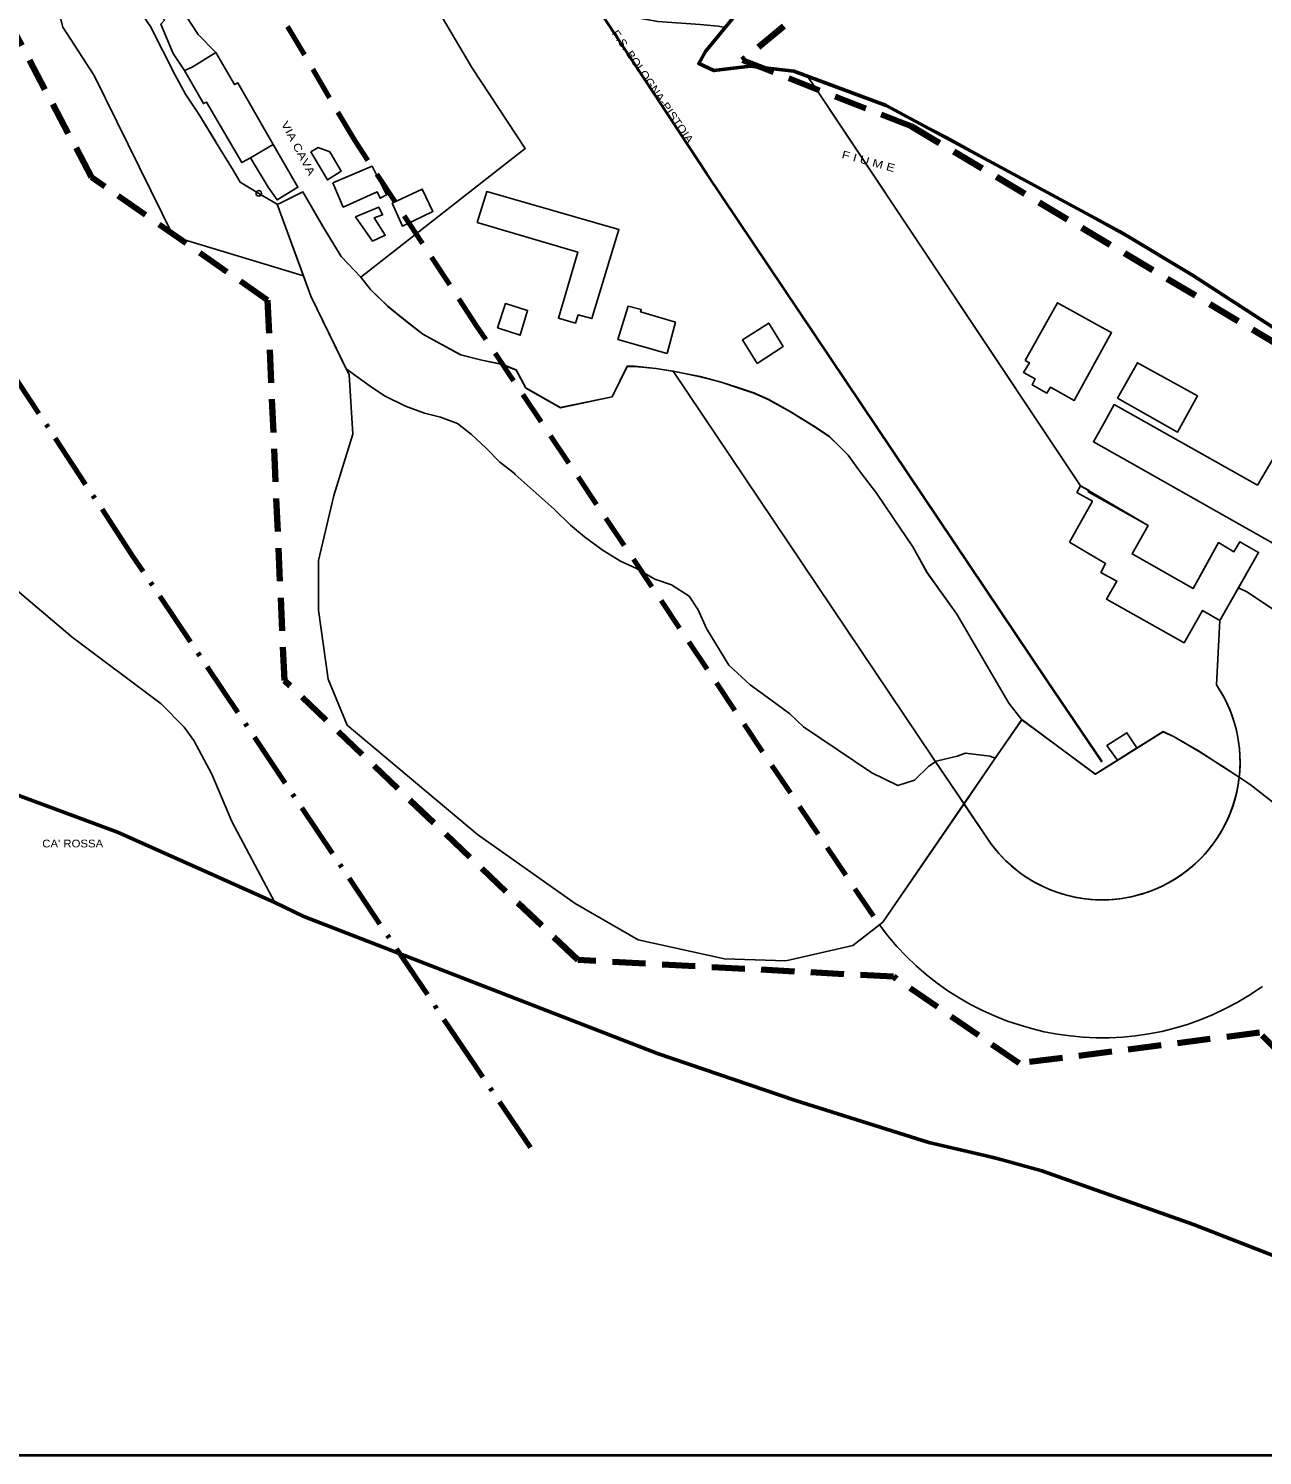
# Model space of a CAD drawing. Extents: x 654952 to 658955, y 890426 to 894481.
# Drawn here: x 658161 to 658609, y 890426 to 890943 of the extents above; entities that cross this region are included whole.
import ezdxf

# ---------------------------------------------------------------- set-up
doc = ezdxf.new("R2010")
doc.units = 0
doc.header["$LTSCALE"] = 4
doc.header["$PDMODE"] = 32
doc.header["$PDSIZE"] = 2
doc.linetypes.add('DOT_DASHED', pattern=[7.7, 5, -1.2, 0.3, -1.2])
doc.linetypes.add('MEDIUM_DASHED', pattern=[4.5, 3, -1.5])
for name, color, linetype, lineweight in [('1', 7, 'Continuous', 25), ('29', 7, 'Continuous', 25), ('35', 7, 'Continuous', 25), ('4', 7, 'Continuous', 25), ('45', 7, 'Continuous', 25), ('55', 7, 'Continuous', 25), ('59', 7, 'Continuous', 53), ('6', 7, 'Continuous', 25), ('60', 7, 'Continuous', 35), ('7', 7, 'MEDIUM_DASHED', 100)]:
    doc.layers.add(name, color=color, linetype=linetype, lineweight=lineweight)
doc.layers.add('58', color=7, linetype='Continuous')

msp = doc.modelspace()

# ---------------------------------------------------------------- linework, layer by layer
at = {"layer": '1'}
msp.add_line((658453.98, 890910.72), (658542.85, 890777.44), dxfattribs=at)
for points in [[(658144.37, 890983.94), (658154.14, 890977.98), (658161.52, 890990.5), (658162.91, 890989.74), (658177.71, 890975.4), (658182.65, 890970.82), (658190.16, 890960.7), (658196.63, 890954.23), (658203.08, 890947.87), (658204.42, 890945.86), (658205.72, 890943.95), (658214.64, 890926.33)], [(658404.44, 890930.41), (658406.91, 890934.75), (658414.05, 890943.51), (658411.52, 890943.99), (658404.98, 890944.67), (658389.6, 890945.68), (658372.54, 890948.71), (658364.14, 890949.78), (658351.24, 890952.81), (658343.66, 890956.03), (658335.11, 890960.84)], [(658423.05, 890929.48), (658409.9, 890927.87), (658404.44, 890930.41)], [(658734.45, 890511.82), (658722.78, 890480.06), (658736.33, 890473.12), (658752.96, 890521.61), (658761.95, 890519.26), (658765.57, 890535.45), (658773.72, 890567.09), (658775.59, 890594.61), (658758.58, 890658.97), (658744.97, 890694.47), (658733.05, 890720.87), (658710.93, 890746.45), (658684.67, 890777.43), (658645.53, 890812.09), (658603.84, 890840.99), (658568.96, 890862.45), (658494.56, 890903.83), (658472.38, 890915.2), (658438.87, 890927.61), (658423.05, 890929.48)], [(658214.64, 890926.33), (658218.42, 890919.34), (658223.22, 890912.19), (658229.44, 890902.01), (658235.67, 890891.84), (658238.22, 890887.44), (658244.95, 890883.42)], [(658645.53, 890812.09), (658603.84, 890840.99), (658568.96, 890862.45), (658494.56, 890903.83), (658472.38, 890915.2), (658443.99, 890925.71), (658448.98, 890918.22), (658453.98, 890910.72)], [(658600.07, 890740.44), (658603.34, 890738.83), (658624.52, 890724.75), (658645.68, 890709.35), (658672.24, 890689.64), (658686.53, 890672.4), (658723.74, 890628.69), (658738.84, 890615.48), (658747.88, 890610.82), (658767.93, 890596.66), (658775.17, 890588.4), (658775.59, 890594.61), (658758.58, 890658.97), (658744.97, 890694.47), (658733.05, 890720.87), (658710.93, 890746.45), (658684.67, 890777.43), (658645.53, 890812.09), (658603.84, 890840.99), (658568.96, 890862.45), (658494.56, 890903.83), (658472.38, 890915.2), (658443.99, 890925.71)], [(658443.99, 890925.71), (658448.98, 890918.22), (658453.98, 890910.72)], [(658453.98, 890910.72), (658542.85, 890777.44), (658567.33, 890763), (658561.5, 890752.72), (658583.67, 890740.2), (658587.28, 890746.72)], [(658244.95, 890883.42), (658251.66, 890879.46), (658252.47, 890879.79), (658260.92, 890883.93), (658268.23, 890871.33), (658274.77, 890860.54), (658281.88, 890853.09)], [(658281.88, 890853.09), (658285.47, 890848.53), (658291.76, 890842.46), (658298.59, 890836.8), (658304.4, 890832.38), (658318.14, 890824.87), (658325.82, 890822.96), (658333.13, 890821.39), (658338.29, 890819.37)], [(658338.29, 890819.37), (658341.72, 890812.83), (658354.26, 890805.72), (658372.98, 890809.62), (658378.45, 890820.71), (658381.12, 890820.68)], [(658381.12, 890820.68), (658388.94, 890819.92), (658396.93, 890818.61), (658404.94, 890816.93), (658412.6, 890814.98), (658418.22, 890813.07), (658424.38, 890811.03), (658429.56, 890808.76), (658437.64, 890804.27), (658446.06, 890799.09), (658451.75, 890795.25), (658455.7, 890791.41), (658458.64, 890788.49)], [(658458.64, 890788.49), (658463.32, 890782.05), (658468.89, 890774.79), (658474.93, 890765.75), (658482.01, 890755.23), (658487.22, 890745.92), (658497.95, 890730.82), (658516.82, 890698.56), (658521.53, 890692.55), (658548.19, 890672.82), (658572.74, 890688.25)], [(658542.85, 890777.44), (658567.33, 890763), (658561.5, 890752.72), (658583.67, 890740.2), (658587.28, 890746.72)], [(658587.28, 890746.72), (658592.87, 890756.8), (658598.39, 890753.48), (658600.55, 890757.16), (658607.33, 890753.26), (658600.07, 890740.44)], [(658587.28, 890746.72), (658592.87, 890756.8), (658598.39, 890753.48), (658600.55, 890757.16), (658607.33, 890753.26), (658600.07, 890740.44)], [(658600.07, 890740.44), (658603.34, 890738.83), (658624.52, 890724.75)], [(658572.74, 890688.25), (658576.75, 890686.35), (658585.54, 890681.27), (658593.98, 890675.84), (658604.34, 890669.07), (658613.77, 890661.75)]]:
    msp.add_lwpolyline(points, dxfattribs=at)
msp.add_point((658244.95, 890883.42), dxfattribs=at)
at = {"layer": '29'}
for p, q in [((658396.9, 890818.66), (658396.93, 890818.61)), ((658474.9, 890765.8), (658468.89, 890774.79)), ((658497.92, 890730.87), (658487.2, 890745.96)), ((658489.14, 890679.06), (658490.26, 890677.4)), ((658500.57, 890662.11), (658490.26, 890677.4))]:
    msp.add_line(p, q, dxfattribs=at)
for points in [[(658395.2, 890818.94), (658388.91, 890819.97), (658381.09, 890820.73), (658378.42, 890820.76), (658372.98, 890809.62), (658354.23, 890805.77), (658341.69, 890812.88), (658338.26, 890819.42), (658333.09, 890821.49), (658325.79, 890823.01), (658318.11, 890824.92), (658304.37, 890832.43), (658298.56, 890836.85), (658291.73, 890842.51), (658285.44, 890848.58), (658281.88, 890853.09), (658274.77, 890860.54), (658268.2, 890871.38), (658260.92, 890883.93), (658252.47, 890879.79), (658251.66, 890879.46), (658263.82, 890846.16), (658276.67, 890819.81)], [(658276.67, 890819.81), (658277.7, 890817.69), (658279.08, 890796.16), (658272.14, 890773.94), (658266.59, 890750.33), (658266.59, 890732.27), (658270.06, 890707.27), (658277, 890690.61), (658324.2, 890651.02)], [(658490.26, 890677.4), (658487.87, 890675.79), (658482.63, 890670.75), (658476.58, 890668.78), (658467.21, 890673.37), (658442.34, 890690.05), (658437.4, 890694.69), (658430.6, 890699.87), (658423.01, 890705.28), (658415.29, 890712.39), (658407.26, 890725.63), (658404.27, 890732.41), (658400.96, 890737.37), (658394.56, 890741.53), (658388.54, 890743.54), (658381.83, 890747.44), (658376.12, 890750.06), (658369.83, 890753.97), (658363.04, 890758.93), (658357.94, 890763.17), (658352.05, 890768.92), (658337.9, 890781.56), (658337.56, 890781.98), (658332.37, 890785.95), (658327.42, 890791.08), (658322.07, 890795.98), (658317.01, 890799.98), (658310.76, 890802.35), (658305.01, 890803.78), (658298.1, 890806.25), (658290.57, 890810.05), (658285.35, 890813.58), (658280.14, 890817.31), (658276.67, 890819.81)], [(658276.67, 890819.81), (658280.14, 890817.31), (658285.35, 890813.58), (658290.57, 890810.05), (658298.1, 890806.25), (658305.01, 890803.78), (658310.76, 890802.35), (658317.01, 890799.98), (658322.07, 890795.98), (658327.42, 890791.08), (658332.37, 890785.95), (658337.56, 890781.98), (658337.9, 890781.56), (658352.05, 890768.92), (658357.94, 890763.17), (658363.04, 890758.93), (658369.83, 890753.97), (658376.12, 890750.06)], [(658396.9, 890818.66), (658395.2, 890818.94), (658489.14, 890679.06)], [(658490.26, 890677.4), (658489.14, 890679.06), (658395.2, 890818.94)], [(658429.58, 890808.78), (658429.53, 890808.81), (658424.34, 890811.13), (658418.19, 890813.12), (658412.57, 890815.03), (658404.9, 890817.03), (658396.9, 890818.66)], [(658429.56, 890808.76), (658424.38, 890811.03), (658418.22, 890813.07), (658412.6, 890814.98), (658404.94, 890816.93), (658396.93, 890818.61)], [(658396.93, 890818.61), (658404.94, 890816.93), (658412.6, 890814.98), (658418.22, 890813.07), (658424.38, 890811.03), (658429.56, 890808.76), (658429.58, 890808.78)], [(658458.61, 890788.54), (658451.71, 890795.35), (658446.03, 890799.14), (658437.61, 890804.32), (658429.58, 890808.78)], [(658468.89, 890774.79), (658463.32, 890782.05), (658458.64, 890788.49)], [(658487.2, 890745.96), (658482.01, 890755.23), (658474.93, 890765.75)], [(658376.12, 890750.06), (658381.83, 890747.44), (658388.54, 890743.54), (658394.56, 890741.53), (658400.96, 890737.37), (658404.27, 890732.41), (658407.26, 890725.63), (658415.29, 890712.39), (658423.01, 890705.28), (658430.6, 890699.87), (658437.4, 890694.69), (658442.34, 890690.05), (658467.21, 890673.37), (658476.58, 890668.78), (658482.63, 890670.75), (658487.87, 890675.79), (658490.26, 890677.4)], [(658511.91, 890678.63), (658521.5, 890692.6), (658516.8, 890698.6), (658497.95, 890730.82)], [(658490.26, 890677.4), (658490.48, 890677.55), (658498.07, 890679.43), (658501.06, 890680.49), (658509.93, 890679.39), (658511.91, 890678.63)], [(658500.57, 890662.11), (658511.91, 890678.63), (658509.93, 890679.39), (658501.06, 890680.49), (658498.07, 890679.43)], [(658498.07, 890679.43), (658490.48, 890677.55), (658490.26, 890677.4), (658500.57, 890662.11)], [(658324.2, 890651.02), (658359.59, 890626.02), (658382.5, 890612.83), (658413.73, 890605.89), (658435.94, 890605.19), (658460.23, 890610.75), (658471.13, 890619.23), (658500.57, 890662.11)]]:
    msp.add_lwpolyline(points, dxfattribs=at)
at = {"layer": '35'}
for p, q in [((658229.41, 890902.06), (658223.22, 890912.19)), ((658261.14, 890853.52), (658213.99, 890867.74)), ((658509.2, 890649.33), (658500.57, 890662.11))]:
    msp.add_line(p, q, dxfattribs=at)
for points in [[(658213.99, 890867.74), (658185.33, 890926.17), (658173.89, 890943.74), (658167.04, 890971.14), (658161.52, 890990.5), (658154.14, 890977.98), (658144.37, 890983.94), (658152.75, 890997.52), (658139.53, 891006.49)], [(658161.52, 890990.5), (658167.04, 890971.14), (658173.89, 890943.74), (658185.33, 890926.17), (658213.99, 890867.74)], [(658223.22, 890912.19), (658218.42, 890919.34), (658214.64, 890926.33), (658205.72, 890943.95), (658204.42, 890945.86), (658203.08, 890947.87)], [(658244.95, 890883.42), (658238.22, 890887.44), (658235.67, 890891.84), (658229.44, 890902.01)], [(658213.99, 890867.74), (658261.14, 890853.52), (658251.66, 890879.46), (658244.95, 890883.42)], [(658044.62, 890869.41), (658053.99, 890858.05), (658072.44, 890837.18), (658093.46, 890800.73), (658145.37, 890749.45), (658177.27, 890722.55), (658209.51, 890698.32), (658217.94, 890689.89), (658221.35, 890685.08), (658227.97, 890672.83), (658235.17, 890655.67), (658250.77, 890626.38), (658261.33, 890621.22), (658389.5, 890571.65), (658439.45, 890554.58)], [(658469.92, 890618.28), (658460.23, 890610.75), (658435.94, 890605.19), (658413.73, 890605.89), (658382.5, 890612.83), (658359.59, 890626.02), (658324.2, 890651.02), (658277, 890690.61), (658270.06, 890707.27), (658266.59, 890732.27), (658266.59, 890750.33), (658272.14, 890773.94), (658279.08, 890796.16), (658277.7, 890817.69), (658263.82, 890846.16), (658261.14, 890853.52)], [(658064.38, 890699.85), (658193.76, 890651.87), (658250.77, 890626.38), (658235.17, 890655.67), (658227.97, 890672.83), (658221.35, 890685.08), (658217.94, 890689.89), (658209.51, 890698.32), (658177.27, 890722.55), (658145.37, 890749.45)], [(658600.33, 890671.74), (658593.94, 890675.94), (658585.51, 890681.32), (658576.71, 890686.45), (658572.71, 890688.3), (658548.15, 890672.92), (658521.49, 890692.65), (658500.56, 890662.13), (658509.2, 890649.33)], [(658613.74, 890661.8), (658604.31, 890669.12), (658600.33, 890671.74)], [(658500.56, 890662.13), (658471.13, 890619.23), (658469.92, 890618.28)], [(658439.45, 890554.58), (658487.84, 890539.37), (658528.8, 890529.12), (658583.71, 890509.56), (658626.83, 890492.8), (658673.05, 890479.76), (658699.42, 890463), (658709.42, 890459.89)]]:
    msp.add_lwpolyline(points, dxfattribs=at)
for radius, start, end in [(50, 292.3219, 353.6142), (50, 304.0044, 353.6142), (50, 214.0081, 292.3219), (50, 214.0081, 292.3219), (50, 292.3219, 304.0044), (100, 216.1693, 305.0715), (100, 216.1693, 305.0715), (100, 305.0715, 305.5264), (100, 305.0715, 305.5264)]:
    msp.add_arc((658550.64, 890677.3), radius, start, end, dxfattribs=at)
msp.add_point((658244.95, 890883.42), dxfattribs=at)
at = {"layer": '4'}
for points in [[(658229.43, 890934.5), (658220.79, 890929.13), (658218.02, 890927.98), (658224.88, 890915.98), (658226, 890916.5), (658238.81, 890894.62), (658241.96, 890896.28), (658250.2, 890901.18), (658237.34, 890923.5), (658236.18, 890922.84)], [(658241.96, 890896.28), (658250.2, 890901.18), (658256.38, 890890.48), (658259.16, 890885.64), (658251.6, 890881.06), (658248.37, 890885.62)], [(658263.81, 890898.54), (658266.51, 890900), (658270.7, 890898.48), (658274.82, 890891.54), (658269.8, 890888.28)], [(658271.77, 890887.24), (658286.02, 890893.28), (658290.15, 890885.02), (658291.25, 890882.84), (658288.89, 890881.64), (658287.8, 890884), (658275.59, 890878.46)], [(658293.31, 890879.88), (658297.08, 890871.54), (658308.08, 890876.86), (658304.23, 890884.98)], [(658293.31, 890879.88), (658304.23, 890884.98), (658308.08, 890876.86), (658297.08, 890871.54)], [(658293.31, 890879.88), (658304.23, 890884.98), (658308.08, 890876.86), (658297.08, 890871.54)], [(658324.09, 890872.82), (658327.6, 890884.08), (658375.48, 890870.3), (658365.69, 890838.04), (658360.7, 890839.38), (658359.71, 890836.38), (658353.55, 890838.16), (658360.65, 890862.06)], [(658279.98, 890874.94), (658288.44, 890878.44), (658289.81, 890875.62), (658286.79, 890874.54), (658290.77, 890868.22), (658286.17, 890866.14)], [(658331.53, 890834.7), (658334.36, 890843.48), (658342.38, 890841), (658339.66, 890832.02)], [(658392.96, 890825.38), (658375.11, 890830.46), (658378.81, 890842.5), (658383.61, 890841.28), (658383.37, 890840.54), (658395.98, 890836.74)], [(658522.79, 890822.84), (658534.42, 890843.8), (658551.49, 890834.38), (658554.06, 890832.96), (658540.53, 890808.34), (658531.87, 890813.14), (658530.64, 890811.04), (658525.25, 890814.06), (658526.4, 890816.16), (658522.19, 890818.5), (658524.25, 890822.04)], [(658425.54, 890821.7), (658420.27, 890830.28), (658429.77, 890836.34), (658435, 890827.96)], [(658556.25, 890809.14), (658563.42, 890822.04), (658585.22, 890810.02), (658577.95, 890796.84)], [(658538.83, 890756.94), (658547.09, 890771.88), (658541.52, 890775.04), (658542.85, 890777.44), (658545.9, 890775.72), (658545.59, 890775.18), (658567.33, 890763), (658561.5, 890752.72), (658583.67, 890740.2), (658592.87, 890756.8), (658598.39, 890753.48), (658600.55, 890757.16), (658607.33, 890753.26), (658593.32, 890728.54), (658587.06, 890732.24), (658580.41, 890720.52), (658552.22, 890736.36), (658555.93, 890742.9), (658550.17, 890746.04), (658551.86, 890749.22)], [(658552.34, 890683.32), (658556.16, 890677.9), (658563.26, 890682.36), (658559.64, 890687.9)]]:
    msp.add_lwpolyline(points, close=True, dxfattribs=at)
for points in [[(658551.32, 890800.26), (658554.98, 890806.86), (658606.97, 890777.62)], [(658558.02, 890787.4), (658547.5, 890793.3), (658551.32, 890800.26)], [(658606.97, 890777.62), (658613.61, 890788.88), (658640.7, 890773.92), (658627.61, 890750.42), (658619.84, 890754.54), (658618.89, 890753.02), (658558.02, 890787.4)]]:
    msp.add_lwpolyline(points, dxfattribs=at)
at = {"layer": '45', "linetype": 'MEDIUM_DASHED', "lineweight": 70}
msp.add_lwpolyline([(658467.75, 890621.37), (658447.66, 890651.14), (658324.04, 890835.2), (658279.74, 890902.58), (658248.15, 890956.2), (658220.13, 891019.53), (658157.73, 891276.4)], dxfattribs=at)
at = {"layer": '45', "linetype": 'DOT_DASHED', "lineweight": 70}
msp.add_lwpolyline([(658343.4, 890537.48), (658323.23, 890567.38), (658199.11, 890752.18), (658152.38, 890823.25), (658114.5, 890887.55), (658077.53, 890971.09), (658011.97, 891240.99)], dxfattribs=at)
at = {"layer": '45', "lineweight": 40}
msp.add_lwpolyline([(658550.65, 890677.3), (658530.62, 890706.98), (658407.33, 890890.55), (658364.65, 890955.46), (658337.25, 891001.97), (658315.22, 891051.75), (658272.64, 891227.84)], dxfattribs=at)
msp.add_lwpolyline([(658550.65, 890677.3), (658530.62, 890706.98), (658407.33, 890890.55), (658364.65, 890955.46), (658337.25, 891001.97), (658315.22, 891051.75), (658272.64, 891227.84)], dxfattribs=at)
at = {"layer": '45'}
for points in [[(658509.2, 890649.33), (658489.14, 890679.06), (658395.17, 890818.98), (658388.91, 890819.97), (658381.09, 890820.73), (658378.45, 890820.71), (658372.98, 890809.62), (658354.26, 890805.72), (658341.72, 890812.83), (658338.29, 890819.37), (658333.13, 890821.39), (658325.82, 890822.96), (658318.14, 890824.87), (658304.4, 890832.38), (658291.76, 890842.46), (658285.47, 890848.53), (658281.88, 890853.09), (658341.53, 890899.7), (658322.2, 890929.02), (658292.7, 890979.09)], [(658430.14, 890963.41), (658406.87, 890934.85), (658404.4, 890930.51), (658409.9, 890927.87), (658423.01, 890929.58), (658438.87, 890927.61), (658443.99, 890925.71), (658448.98, 890918.22), (658542.85, 890777.44), (658567.33, 890763), (658561.5, 890752.72), (658583.67, 890740.2), (658592.87, 890756.8), (658598.39, 890753.48), (658600.55, 890757.16), (658607.33, 890753.26), (658593.32, 890728.54), (658592.09, 890705.26)]]:
    msp.add_lwpolyline(points, dxfattribs=at)
msp.add_arc((658550.64, 890677.3), 50, 214.0081, 34.0006, dxfattribs=at)
at = {"layer": '55'}
msp.add_line((658509.2, 890649.33), (658500.57, 890662.11), dxfattribs=at)
for points in [[(658274.77, 890860.54), (658281.88, 890853.09), (658285.47, 890848.53), (658281.88, 890853.09), (658341.53, 890899.7), (658322.2, 890929.02), (658308.09, 890952.97)], [(658173.89, 890943.74), (658185.33, 890926.17), (658213.99, 890867.74), (658261.14, 890853.52), (658251.66, 890879.46), (658252.47, 890879.79), (658260.92, 890883.93), (658268.2, 890871.38), (658274.77, 890860.54)], [(658600.07, 890740.44), (658593.32, 890728.54), (658592.09, 890705.26)], [(658775.17, 890588.4), (658767.93, 890596.66), (658747.88, 890610.82), (658738.84, 890615.48), (658723.74, 890628.69), (658686.53, 890672.4), (658672.24, 890689.64), (658645.68, 890709.35), (658624.52, 890724.75), (658603.34, 890738.83), (658600.07, 890740.44)], [(658500.57, 890662.11), (658471.13, 890619.23), (658469.92, 890618.28)]]:
    msp.add_lwpolyline(points, dxfattribs=at)
for radius, start, end in [(50, 292.3219, 34.0006), (50, 214.0081, 292.3219), (100, 216.1693, 305.0715), (100, 305.0715, 305.5264)]:
    msp.add_arc((658550.64, 890677.3), radius, start, end, dxfattribs=at)
at = {"layer": '59'}
for points in [[(658320.32, 891243.1), (658316.29, 891187.54), (658329.01, 891148.11), (658333.04, 891120.79), (658342.35, 891092.85), (658409.36, 890996.94), (658412.46, 890992.59), (658417.73, 890987.93), (658430.14, 890963.41), (658406.88, 890934.85), (658404.4, 890930.51), (658409.86, 890927.97), (658423.01, 890929.57), (658438.83, 890927.71), (658472.34, 890915.29), (658557.03, 890869.66)], [(658557.03, 890869.66), (658583.4, 890853.83), (658618.77, 890830.85)], [(658626.83, 890492.8), (658583.71, 890509.56), (658528.8, 890529.12), (658511.73, 890533.78), (658487.84, 890539.36), (658439.45, 890554.58), (658389.5, 890571.65), (658261.33, 890621.22), (658250.77, 890626.38), (658230.04, 890635.65), (658193.76, 890651.87), (658064.38, 890699.85)]]:
    msp.add_lwpolyline(points, dxfattribs=at)
at = {"layer": '6'}
msp.add_lwpolyline([(658205.87, 890951.78), (658210.83, 890946.27), (658209.42, 890944.8), (658213.96, 890934.17), (658218.02, 890927.98), (658220.79, 890929.13), (658229.43, 890934.5), (658223, 890941.03), (658216.15, 890951.53), (658213.67, 890949.7), (658208.77, 890954.82)], close=True, dxfattribs=at)
at = {"layer": '60', "lineweight": 40}
msp.add_lwpolyline([(657055.17, 894480.74), (658955.28, 894480.74), (658955.28, 890425.88), (657055.17, 890425.88)], close=True, dxfattribs=at)
at = {"layer": '7'}
msp.add_lwpolyline([(658330.3, 891246.22), (658327.72, 891183.18), (658338.55, 891136.81), (658353.44, 891095.71), (658449.21, 890955.48), (658420.28, 890931.68), (658481.44, 890907.81), (658636.65, 890815.27), (658732.37, 890716.91), (658771.82, 890588.13), (658747.24, 890482.65), (658726.56, 890461.94), (658714.04, 890498.12), (658642.13, 890543.72), (658607.69, 890579.19), (658520.59, 890568.04), (658475.02, 890599.46), (658360.56, 890605.54), (658254.22, 890706.88), (658248.14, 890844.7), (658184.33, 890889.29), (658123.56, 891003.8)], dxfattribs=at)

# ---------------------------------------------------------------- texts
at = {"layer": '58'}
for s, height, rotation, width, p in [('F.S. BOLOGNA-PISTOIA', 2.798, 304.533, 1.15, (658372.77, 890941.47)), ('F.S. BOLOGNA-PISTOIA', 2.798, 304.533, 1.15, (658372.77, 890941.47)), ('VIA CAVA', 2.8, 298.138, 1.25, (658252.91, 890908.64)), ('F I U M E', 2.801, 344.801, 1.25, (658456.04, 890896.31))]:
    msp.add_text(s, height=height, rotation=rotation, dxfattribs=dict(at, width=width)).set_placement(p)
at = {"layer": '58', "width": 1.1}
msp.add_text("CA' ROSSA", height=2.801, dxfattribs=at).set_placement((658166.47, 890646.32))

doc.saveas('drawing.dxf')
